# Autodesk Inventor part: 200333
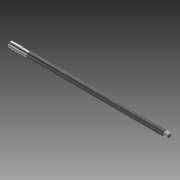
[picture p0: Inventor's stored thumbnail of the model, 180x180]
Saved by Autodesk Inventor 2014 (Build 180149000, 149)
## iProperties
Created: 2007-10
Part Number: 200333
Document SubType Name: Modeling
Designer: TH
Density: 8.08 g/cm^3
Mass: 247.346 g
Surface Area: 113.8 cm^2
Volume: 30.6121 cm^3
Material: Stainless Steel
Description: BALL SCREW SHAFT
Appearance: Chrome - Polished
Component Category: Lower Component
Author: TH
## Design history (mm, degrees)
sketch "Sketch1"
  geometry: L1 (-64.9, 0)-(389.4, 0) reference; L2 (0, 6.636)-(0, -1.106) reference; L3 (0, 0)-(0, 5.53); L4 (0, 5.53)-(3.25, 5.53); L5 (3.25, 5.53)-(3.25, 5.03); L6 (3.25, 5.03)-(5.25, 5.03); L7 (5.25, 5.03)-(5.25, 5.53); L8 (5.25, 5.53)-(22.75, 5.53); L9 (22.75, 5.53)-(22.75, 5.03); L10 (22.75, 5.03)-(37.75, 5.03); L11 (37.75, 5.03)-(37.75, 5.53); L12 (37.75, 5.53)-(320, 5.53); L13 (320, 5.53)-(320, 4); L14 (320, 4)-(324.5, 4); L15 (324.5, 4)-(324.5, 0); L16 (0, 0)-(324.5, 0)
  constraints: 28 end point, 7 parallel, 5 collinear, 3 perpendicular, 2 point on line
  dimensions: "d0" = 37.75 distance between parallel lines of L11 L2; "d1" = 15 distance between parallel lines of L11 L9; "d2" = 17.5 distance of L7.end L8.end; "d3" = 2 distance from line of L5 L6.end; "d4" = 11.06 diameter of L12 L16; "d5" = 0.5 distance between parallel lines of L8 L6; "d6" = 0.5 distance between parallel lines of L8 L10 (= d5); "d7" = 320 distance between parallel lines of L3 L13; "d8" = 324.5 distance between parallel lines of L3 L15; "d9" = 8 diameter of L14 L16
revolve "Revolution1" sketch "Sketch1" stored, may be unused: angle "d10" = 90 deg
chamfer "Chamfer1" distance "d11" = 1.53; stored, may be unused: second distance "d12" = 3, angle "d13" = 45 deg
chamfer "Chamfer2" distance "d14" = 0.5; stored, may be unused: second distance "d15" = 3, angle "d16" = 45 deg
thread "Thread1" dims "d17" = 10, "d18" = 0
body "Solid1"
